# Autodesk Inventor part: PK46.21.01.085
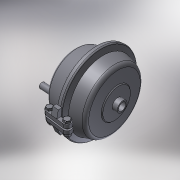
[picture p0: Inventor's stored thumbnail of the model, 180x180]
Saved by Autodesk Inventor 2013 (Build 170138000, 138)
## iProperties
Created: 2005-03
Part Number: PK46.21.01.085
Material: Steel, Mild
Document SubType Name: Modeling
Designer: salex
Manufacturer: Standard
Standards Organization: Custom
Density: 7.86 g/cm^3
Mass: 18779.2 g
Surface Area: 1282.96 cm^2
Volume: 2389.21 cm^3
Author: salex
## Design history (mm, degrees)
feature "Sculpt1"
body "Solid2"
feature "Surface1"
body "Srf1"
